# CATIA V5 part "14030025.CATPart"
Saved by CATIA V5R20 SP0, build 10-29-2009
Part number: 14030025
Definition: NONE
Nomenclature: 14030025
Source: Unknown
Description: 14030025
Bounding box of the stored display mesh (mm): x -12.5 to 50, y -29 to 18.906, z -19.1 to 19.1
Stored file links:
  C:\Users\Utente\Desktop\IO LAVORO\3D X SITO CF\X SITO\PLASTICA\RF2\14030025.CATPart
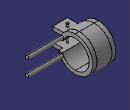
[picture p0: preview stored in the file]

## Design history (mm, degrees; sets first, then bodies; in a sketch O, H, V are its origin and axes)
Body1 "14030025" (main body)
  Solid1: solid without history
